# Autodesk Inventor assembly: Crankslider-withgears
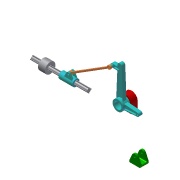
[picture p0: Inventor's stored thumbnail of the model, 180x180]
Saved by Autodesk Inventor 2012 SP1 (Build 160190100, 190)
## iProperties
Shininess: 64.0
Angle Display Precision: 2
Document Length Units: 11272
Document Angle Units: 11279
Document Time Units: 11290
Document Mass Units: 11286
Document Length Units Precision: 3
Document Angle Units Precision: 2
Created: 2008-04
Part Number: Crankslider-withgears
Document SubType Name: Assembly
Designer: wyounis
Mass: 1262.32 g
Surface Area: 548.228 cm^2
Volume: 159.853 cm^3
Density: 7.89671 g/cm^3
Density: 0.0
Volumn: 0.0
Area: 0.0
PropertySet Name: Model Information
Control State: 0
Master: False
Checked Out: False
Author: wyounis
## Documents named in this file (8)
- D:\Backup\CMU Work Temp\XX\Crank Slider Mechanism.iam
- D:\Backup\CMU Work Temp\XX\Con-arm.ipt
- D:\Backup\CMU Work Temp\XX\Con-arm-Housing.ipt
- D:\Backup\CMU Work Temp\XX\link-2.ipt
- D:\Backup\CMU Work Temp\XX\slider-shaft.ipt
- D:\Backup\CMU Work Temp\XX\Collar Clevis.ipt
- D:\Backup\CMU Work Temp\XX\Actuator Clevis.ipt
- D:\Backup\CMU Work Temp\XX\Part1.ipt
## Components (7 placed, 7 different names)
1. Con-arm-Housing:1
2. slider-shaft:1 — Mate:13, Angle:1, Mate:22, Flush:1
3. Con-arm:1 — Mate:21, Angle:2
4. link-2:1 — Mate:14, Mate:15, Mate:21
5. Collar Clevis:1 — Mate:13, Angle:1, Mate:14, Mate:15
6. Actuator Clevis:1 — Angle:2
7. Part1:1 — Mate:22, Flush:1
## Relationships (8: Mate 5, Angle 2, Flush 1)
- Mate:13: slider-shaft:1 ↔ Collar Clevis:1
- Angle:1: slider-shaft:1 ↔ Collar Clevis:1
- Mate:14: link-2:1 ↔ Collar Clevis:1
- Mate:15: link-2:1 ↔ Collar Clevis:1
- Mate:21: Con-arm:1 ↔ link-2:1
- Angle:2: Con-arm:1 ↔ Actuator Clevis:1
- Mate:22: slider-shaft:1 ↔ Part1:1
- Flush:1: slider-shaft:1 ↔ Part1:1
